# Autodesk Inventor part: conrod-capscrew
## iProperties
Created: 2002-08
Part Number: conrod-capscrew
Document SubType Name: Modeling
Designer: t_munrn
Density: 1 g/cm^3
Control State: 0
Master: False
Checked Out: False
Shininess: 64.0
Length Units: 11269
Angle Units: 11279
Time Units: 11290
Mass Units: 11283
Length Display Precision: 3
Angle Display Precision: 2
Density: 0.0
Volumn: 0.0
Area: 0.0
PropertySet Name: Model Information
Author: t_munrn
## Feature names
1. Revolution1
2. Extrusion1
3. Chamfer1
